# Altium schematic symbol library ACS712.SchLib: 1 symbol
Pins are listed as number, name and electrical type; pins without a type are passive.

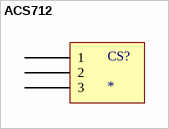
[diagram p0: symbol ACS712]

## ACS712
designator CS?
footprint ACS712
pins: 1, 2, 3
